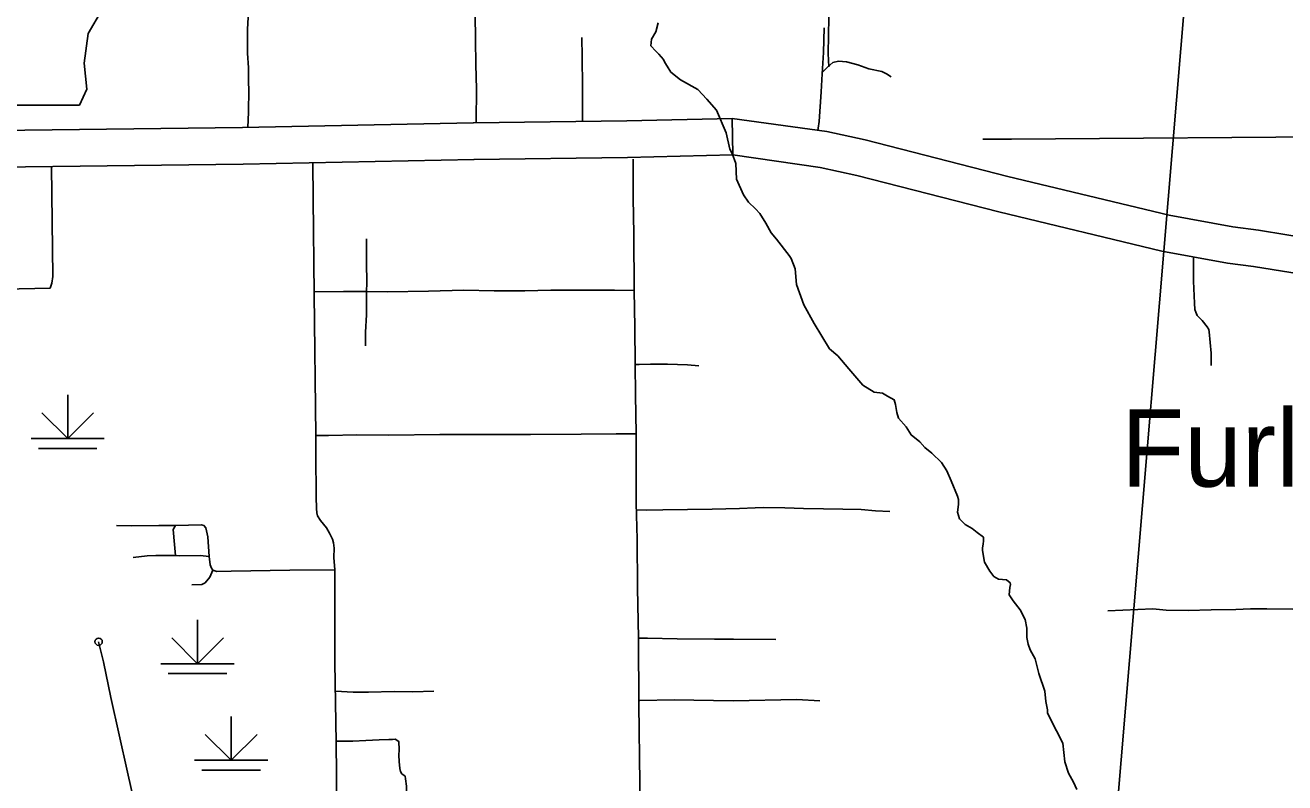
# Model space of a CAD drawing. Extents: x 1127717 to 1741049, y 2026793 to 2244711.
# Drawn here: x 1307075 to 1315678, y 2097463 to 2102640 of the extents above; entities that cross this region are included whole.
import ezdxf

# ---------------------------------------------------------------- set-up
doc = ezdxf.new("R2010")
doc.units = 0
for name, color, linetype in [('10', 7, 'Continuous'), ('21', 7, 'Continuous'), ('24', 7, 'Continuous'), ('31', 7, 'Continuous'), ('32', 7, 'Continuous'), ('35', 7, 'Continuous'), ('4', 7, 'Continuous'), ('43', 7, 'Continuous'), ('44', 7, 'Continuous'), ('45', 7, 'Continuous'), ('R_Draft', 7, 'Continuous')]:
    doc.layers.add(name, color=color, linetype=linetype)

msp = doc.modelspace()

# ---------------------------------------------------------------- linework, layer by layer
at = {"layer": '10'}
for p, q in [((1310135.4, 2101972.9), (1310136.3, 2101972.9)), ((1310139.5, 2101723), (1310140.5, 2101723))]:
    msp.add_line(p, q, dxfattribs=at)
for points in [[(1310136.3, 2101972.9), (1311184.2, 2101986.3), (1311903.3, 2102002.8)], [(1311903.3, 2102002.8), (1311909, 2101752.9)], [(1311909, 2101752.9), (1311903.3, 2102002.8)], [(1311903.3, 2102002.8), (1312549.5, 2101912.6), (1312812.9, 2101856), (1313785.6, 2101606.2), (1314889, 2101340.5), (1315323.6, 2101261.5), (1315499.2, 2101239.4), (1315885.7, 2101176.4), (1316840.1, 2101031.7), (1317158.5, 2100975.1), (1317742.2, 2100880.4)], [(1305956.6, 2101908.9), (1308559.5, 2101940.7), (1310135.4, 2101972.9)], [(1310140.5, 2101723), (1308563.6, 2101690.8), (1305961.8, 2101658.9)], [(1311909, 2101752.9), (1311188.6, 2101736.3), (1310139.5, 2101723)], [(1317700.8, 2100633.8), (1317116.5, 2100728.6), (1316799.5, 2100785), (1315846.8, 2100929.4), (1315463.5, 2100991.9), (1315285.6, 2101014.3), (1314837.3, 2101095.8), (1313725.2, 2101363.6), (1312755.5, 2101612.6), (1312505.6, 2101666.4), (1311909, 2101752.9)]]:
    msp.add_lwpolyline(points, dxfattribs=at)
at = {"layer": '21'}
msp.add_lwpolyline([(1306142.1, 2103682.6), (1306218.2, 2103175), (1306184.4, 2102405.3), (1306252.1, 2102363), (1306379, 2102363), (1306379, 2102092.3), (1307444.8, 2102092.3), (1307495.5, 2102202.2), (1307478.6, 2102379.9), (1307504, 2102582.9), (1307597.1, 2102743.6), (1307656.3, 2102862), (1307740.9, 2102988.9), (1307791.6, 2103124.3), (1307833.9, 2103234.2), (1307910, 2103327.3), (1307927, 2103386.5), (1307893.1, 2103428.8), (1307630.9, 2103428.8), (1307690.1, 2103547.2), (1307698.6, 2103623.3), (1307663.5, 2103681.8)], close=True, dxfattribs=at)
at = {"layer": '31'}
for points in [[(1308596.1, 2101941.2), (1308599, 2102045.6), (1308602.1, 2102199.9), (1308600.5, 2102248.3), (1308599, 2102348.1)], [(1310153.9, 2101973.3), (1310156, 2102040.6), (1310157.2, 2102144.6), (1310157.2, 2102171.5)], [(1311282.7, 2096647.3), (1311274.1, 2097095.9), (1311272.4, 2097460.9), (1311265.6, 2097996.9), (1311263.9, 2098450.6), (1311257.1, 2098794), (1311255.4, 2099126.7), (1311248.6, 2099374), (1311246.9, 2099619.6), (1311246.9, 2099847), (1311243.5, 2100114.8), (1311241.7, 2100322.9), (1311238.3, 2100576.2), (1311234.9, 2100827), (1311231.5, 2101210.8), (1311228.1, 2101460.5), (1311226.5, 2101724.4)], [(1307254, 2101674.7), (1307263.7, 2100921.6), (1307256.2, 2100877.3), (1307245, 2100842.6)], [(1309040.1, 2101700.5), (1309042.1, 2101453.8), (1309047.8, 2100802.4)], [(1309406.8, 2101179), (1309406.8, 2101017.1), (1309408.4, 2100878.7), (1309406.8, 2100818.9), (1309405.2, 2100661.6), (1309398.9, 2100542.1), (1309398.9, 2100449.3)], [(1309047.7, 2100817.3), (1309248, 2100818.9), (1309406.8, 2100818.9), (1309549.9, 2100817.3), (1309829.7, 2100822), (1310071.8, 2100828.3), (1310277.7, 2100823.6), (1310488.4, 2100825.2), (1310664.5, 2100828.3), (1310899.5, 2100828.3), (1311099.1, 2100828.3), (1311234.9, 2100827)], [(1309047.8, 2100802.4), (1309059.4, 2099836.6)], [(1311246.9, 2099847), (1311111.6, 2099847.6), (1310872.6, 2099846), (1310526.7, 2099842.9), (1310160.4, 2099842.9), (1309905.8, 2099842.9), (1309558.3, 2099838.2), (1309339.2, 2099839.7), (1309147.4, 2099835), (1309059.4, 2099836.6)], [(1309059.4, 2099836.6), (1309060.9, 2099709.2), (1309062.5, 2099416.7), (1309064.1, 2099338), (1309065.7, 2099306.6), (1309071.9, 2099287.7), (1309090.8, 2099256.3), (1309131.7, 2099204.4), (1309153.7, 2099168.2), (1309174.1, 2099127.3), (1309180.4, 2099102.1), (1309185.1, 2099066), (1309183.6, 2099001.5), (1309188.5, 2098918.9)], [(1309188.5, 2098918.9), (1308883.3, 2098914.9), (1308481.8, 2098908.9), (1308383.5, 2098906.8), (1308357.4, 2098914.9), (1308347.3, 2098928.9), (1308337.3, 2098953), (1308331.3, 2099009.3), (1308321.2, 2099143.8), (1308309.2, 2099204.1), (1308295.1, 2099222.1), (1308279.1, 2099226.2), (1308100.4, 2099222.1), (1307988, 2099222.1), (1307799.3, 2099218.1), (1307698.9, 2099222.1)], [(1308100.4, 2099015.3), (1308094.4, 2099091.6), (1308086.3, 2099194), (1308100.4, 2099222.1)], [(1308331.3, 2099009.3), (1308269, 2099015.3), (1308128.5, 2099013.3), (1308100.4, 2099015.3), (1308050.2, 2099015.3), (1307965.9, 2099015.3), (1307907.7, 2099013.3), (1307811.3, 2099003.2)], [(1308357.4, 2098914.9), (1308335.3, 2098868.7), (1308303.2, 2098828.5), (1308281.1, 2098818.5), (1308212.8, 2098814.5)], [(1309208.6, 2096626.2), (1309204.5, 2097072.1), (1309198.5, 2097741.2), (1309190.5, 2098281.5), (1309188.5, 2098671.1), (1309188.5, 2098918.9)], [(1314469.8, 2098638.3), (1314777.2, 2098651.3), (1314867, 2098643.2), (1315017.3, 2098640.3), (1315175.6, 2098645.5), (1315344, 2098648), (1315442.6, 2098650.5), (1315554.8, 2098651.7), (1315733.2, 2098649.3), (1315905.3, 2098646.8), (1316098.6, 2098646.8), (1316345.6, 2098645.5), (1316713.8, 2098644.3), (1317103, 2098644.3), (1317480.3, 2098642.8)], [(1307576.4, 2098426.9), (1307608.5, 2098288.3), (1307660.7, 2098045.3), (1307773.2, 2097535.2), (1307857.5, 2097159.6), (1307915.7, 2096895.1), (1307963.9, 2096692.2), (1307969.9, 2096656.1), (1307969.9, 2096620.2)]]:
    msp.add_lwpolyline(points, dxfattribs=at)
msp.add_circle((1307576.4, 2098426.9), 25, dxfattribs=at)
at = {"layer": '32'}
for points in [[(1308599, 2102348.1), (1308593, 2102449.4), (1308593, 2102612.7), (1308600.5, 2102733), (1308614.2, 2102843.4), (1308615.7, 2102914.4), (1308617.2, 2103033.9), (1308627.8, 2103180.6), (1308632.3, 2103278.9), (1308633.8, 2103395.4), (1308636.8, 2103606), (1308641.4, 2103761.8), (1308647.4, 2103896.4), (1308647.4, 2104035.5), (1308653.5, 2104167.1), (1308655, 2104299.3), (1308654.4, 2104326.9)], [(1310157.2, 2102171.5), (1310157.2, 2102203), (1310152.3, 2102371.8), (1310151.1, 2102539.5), (1310148.6, 2102714.4), (1310148.6, 2102832.2), (1310154.8, 2102868.9), (1310173.1, 2102915.4), (1310219.6, 2103023.1), (1310219.6, 2103056.1), (1310217.1, 2103091.6), (1310206.1, 2103141.8), (1310196.3, 2103189.5), (1310191.4, 2103233.5)], [(1312530.9, 2102622.2), (1312526.2, 2102452.8), (1312517.4, 2102306.9), (1312511.2, 2102183.6), (1312497.3, 2101981), (1312491, 2101937), (1312488.9, 2101920.5)], [(1310882.2, 2101982.8), (1310882.2, 2102154.1), (1310882.2, 2102266.6), (1310879.7, 2102376.7), (1310879.7, 2102424.4), (1310876.1, 2102555.4)], [(1315054.4, 2101059), (1315055.5, 2100890.6), (1315060.1, 2100739.4), (1315062.4, 2100696.2), (1315070.3, 2100678), (1315080.5, 2100656.4), (1315113.5, 2100622.3), (1315147.6, 2100579.1), (1315159, 2100560.9), (1315162.4, 2100543.8), (1315169.2, 2100472.2), (1315174.9, 2100399.5), (1315174.9, 2100314.2)], [(1307245, 2100842.6), (1307139.6, 2100841.5), (1306926.6, 2100835), (1306734.3, 2100837.6), (1306552.3, 2100829.9), (1306385.8, 2100831.2), (1306179.2, 2100828.6), (1306085, 2100824.7), (1306033.3, 2100828.6)], [(1311675.9, 2100311.8), (1311598.2, 2100318.4), (1311461, 2100323.4), (1311345.3, 2100323.4), (1311267.6, 2100321.7), (1311241.8, 2100320.1)], [(1312980.8, 2099317.6), (1312883.3, 2099322.3), (1312784.3, 2099330.2), (1312660.1, 2099331.8), (1312528, 2099334.9), (1312391.2, 2099338), (1312262.3, 2099341.2), (1312116.1, 2099344.3), (1312061.1, 2099341.2), (1311954.2, 2099336.5), (1311767.1, 2099331.8), (1311597.3, 2099330.2), (1311430.7, 2099327), (1311315.9, 2099325.5), (1311249.8, 2099328.6)], [(1312201.7, 2098442.1), (1311912.4, 2098443.7), (1311782.2, 2098443.7), (1311527.8, 2098447.3), (1311324.8, 2098450.8), (1311263.9, 2098450.8)], [(1309865.3, 2098089.3), (1309721.5, 2098084.7), (1309595.9, 2098086.2), (1309419.9, 2098083.2), (1309315.8, 2098083.2), (1309193.3, 2098089.3)], [(1311272.7, 2098026), (1311506.6, 2098029.4), (1311911, 2098022.7), (1312345.4, 2098032.7), (1312502.4, 2098022.7)], [(1309648.1, 2097293.4), (1309672.2, 2097331.5), (1309677.2, 2097359.6), (1309678.2, 2097440.9), (1309673.2, 2097491), (1309669.2, 2097508), (1309648.1, 2097525.1), (1309638.1, 2097540.1), (1309634.1, 2097561.2), (1309628.1, 2097609.3), (1309626.1, 2097652.5), (1309628.1, 2097688.6), (1309626.1, 2097745.7), (1309600.8, 2097760.7), (1309583, 2097758.8), (1309557.9, 2097759.8), (1309491.7, 2097756.8), (1309400.5, 2097752.8), (1309313.3, 2097747.7), (1309201, 2097746.7)]]:
    msp.add_lwpolyline(points, dxfattribs=at)
at = {"layer": '35'}
for points in [[(1312391.8, 2100728.9), (1312342.9, 2100868.3), (1312334.6, 2100975.1), (1312305.9, 2101045), (1312293.6, 2101065.5), (1312207.3, 2101176.5), (1312170.4, 2101221.7), (1312133.4, 2101287.4), (1312092.3, 2101353.2), (1312063.6, 2101386), (1312014.3, 2101431.2), (1311981.4, 2101480.5), (1311932.1, 2101587.4), (1311928, 2101694.2), (1311903.4, 2101764.1), (1311886.9, 2101792.8), (1311862.3, 2101903.8), (1311796.6, 2102059.9), (1311730.9, 2102133.9), (1311669.2, 2102199.6), (1311550.1, 2102265.4), (1311484.4, 2102318.8), (1311459.8, 2102359.9), (1311443.3, 2102384.5), (1311435.1, 2102405.1), (1311402.3, 2102442.1), (1311381.7, 2102462.6), (1311348.9, 2102499.6), (1311353, 2102544.8), (1311381.7, 2102594.1), (1311398.2, 2102655.7)], [(1312391.8, 2100728.9), (1312462.7, 2100600.7), (1312569.2, 2100429.2), (1312624.4, 2100379.9), (1312699.2, 2100291.2), (1312795.8, 2100180.8), (1312872.7, 2100131.5), (1312929.8, 2100125.6), (1312965.3, 2100103.9), (1313010.6, 2100080.2), (1313018.5, 2100048.7), (1313028.4, 2099993.5), (1313040.2, 2099954.1), (1313091.5, 2099894.9), (1313126.9, 2099839.7), (1313186.1, 2099792.4), (1313219.6, 2099754.9), (1313266.9, 2099715.5), (1313333.9, 2099650.4), (1313369.3, 2099595.2), (1313398.9, 2099526.2), (1313442.3, 2099421.7), (1313450.2, 2099398.1), (1313450.2, 2099364.5), (1313443.3, 2099312.5), (1313457.1, 2099267.2), (1313494.5, 2099227.7), (1313541.8, 2099200.1), (1313577.3, 2099172.5), (1313620.6, 2099141), (1313620.6, 2099115.3), (1313616.7, 2099093.7), (1313612.8, 2099068), (1313612.8, 2099050.3), (1313626.5, 2098971.4), (1313664, 2098908.3), (1313691.6, 2098872.8), (1313723.1, 2098855.1), (1313778.3, 2098849.2), (1313802, 2098829.5), (1313803.9, 2098817.6), (1313800, 2098797.9), (1313796, 2098746.7), (1313821.7, 2098705.2), (1313870.9, 2098644.1), (1313904.4, 2098579.1), (1313916.3, 2098519.9), (1313916.3, 2098456.8), (1313926.1, 2098409.5), (1313939.9, 2098372.1), (1313973.4, 2098310.9), (1313997.1, 2098209.8), (1314038.5, 2098089.5), (1314046.3, 2098018.5), (1314058.2, 2097961.4), (1314058.2, 2097937.7), (1314119.3, 2097817.4), (1314162.6, 2097734.6), (1314168.5, 2097669.6), (1314176.4, 2097606.5), (1314200.1, 2097529.6), (1314235.6, 2097466.5), (1314257.2, 2097417.2)]]:
    msp.add_lwpolyline(points, dxfattribs=at)
at = {"layer": '4'}
msp.add_lwpolyline([(1313615, 2101861), (1313812.2, 2101861.5), (1316216.9, 2101880)], dxfattribs=at)
at = {"layer": '43'}
msp.add_lwpolyline([(1312520.4, 2102799.2), (1312558.6, 2102786), (1312564.4, 2102692.1), (1312558.6, 2102445.5), (1312564.3, 2102354.2)], dxfattribs=at)
at = {"layer": '44'}
for p, q in [((1307364.8, 2100115), (1307364.8, 2099815)), ((1307364.8, 2099815), (1307188, 2099991.7)), ((1307364.8, 2099815), (1307541.6, 2099991.7)), ((1307114.8, 2099815), (1307614.8, 2099815)), ((1307164.8, 2099746.8), (1307564.8, 2099746.8)), ((1308252.1, 2098576.8), (1308252.1, 2098276.8)), ((1308252.1, 2098276.8), (1308075.3, 2098453.6)), ((1308252.1, 2098276.8), (1308428.8, 2098453.6)), ((1308002.1, 2098276.8), (1308502.1, 2098276.8)), ((1308052.1, 2098208.7), (1308452.1, 2098208.7)), ((1308481.5, 2097916.9), (1308481.5, 2097616.9)), ((1308481.5, 2097616.9), (1308304.7, 2097793.7)), ((1308481.5, 2097616.9), (1308658.3, 2097793.7)), ((1308231.5, 2097616.9), (1308731.5, 2097616.9)), ((1308281.5, 2097548.8), (1308681.5, 2097548.8))]:
    msp.add_line(p, q, dxfattribs=at)
at = {"layer": '45'}
msp.add_lwpolyline([(1312523.4, 2102322.2), (1312553.2, 2102350.6), (1312591.8, 2102384.4), (1312630.3, 2102394), (1312683.3, 2102389.2), (1312762.1, 2102369.9), (1312837.6, 2102341), (1312925.9, 2102323.3), (1312958.1, 2102307.2), (1312990.2, 2102286.3)], dxfattribs=at)
at = {"layer": 'R_Draft'}
msp.add_line((1316275.7, 2118097.7), (1313951.6, 2090343.3), dxfattribs=at)

# ---------------------------------------------------------------- texts
at = {"layer": '24'}
msp.add_text('Furlow', height=528, dxfattribs=at).set_placement((1314560.2, 2099486.6))

doc.saveas('drawing.dxf')
